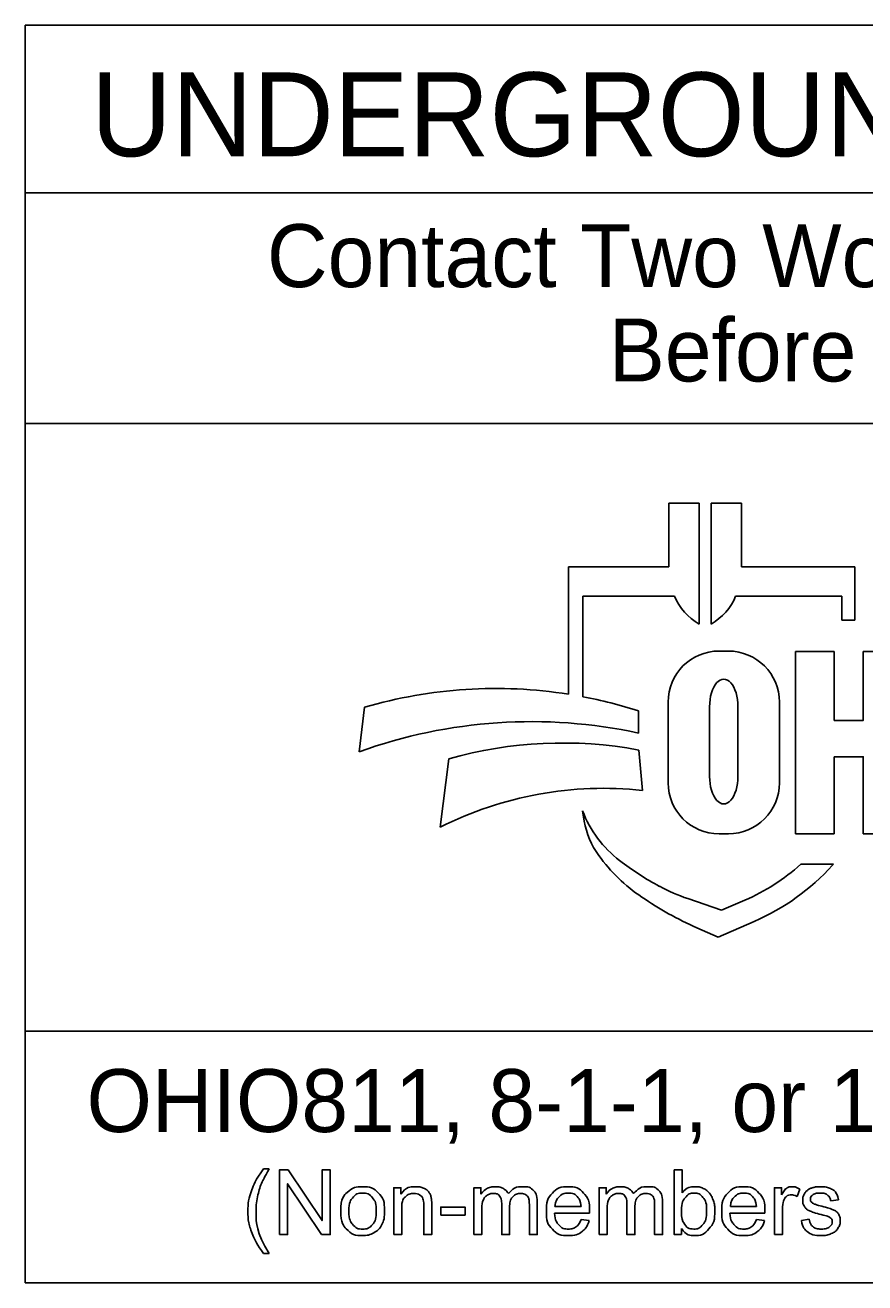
# Model space of a CAD drawing. Extents: x 421.3 to 469.3, y 221.6 to 248.2.
# Drawn here: x 424.333 to 426.536, y 223.579 to 226.879 of the extents above; entities that cross this region are included whole.
import ezdxf

# ---------------------------------------------------------------- set-up
doc = ezdxf.new("R2010")
doc.units = 0
doc.layers.add('SH_Data', color=7, linetype='Continuous')

msp = doc.modelspace()

# ---------------------------------------------------------------- linework, layer by layer
at = {"layer": 'SH_Data'}
for p, q in [((424.3328, 226.8787), (429.5577, 226.8787)), ((424.3328, 223.5787), (424.3328, 226.8787)), ((424.3328, 226.4387), (429.5577, 226.4387)), ((424.3328, 225.8337), (429.5577, 225.8337)), ((426.1017, 225.6241), (426.0216, 225.6241)), ((426.0216, 225.6241), (426.0216, 225.4576)), ((426.1017, 225.3073), (426.1017, 225.6241)), ((426.2129, 225.6241), (426.1328, 225.6241)), ((426.1328, 225.6241), (426.1328, 225.3073)), ((426.2129, 225.4576), (426.2129, 225.6241)), ((426.0216, 225.4576), (425.7587, 225.4576)), ((425.7587, 225.4576), (425.7587, 225.1231)), ((426.5105, 225.4576), (426.2129, 225.4576)), ((426.5105, 225.3174), (426.5105, 225.4576)), ((425.7964, 225.1166), (425.7964, 225.3807)), ((425.7964, 225.3807), (426.0371, 225.3807)), ((426.1973, 225.3807), (426.4758, 225.3807)), ((426.4758, 225.3807), (426.4758, 225.3174)), ((426.4758, 225.3174), (426.5105, 225.3174)), ((426.1784, 225.2364), (426.1537, 225.2364)), ((426.4563, 225.2349), (426.3548, 225.2349)), ((426.3548, 225.2349), (426.3548, 224.7569)), ((426.02, 225.1027), (426.02, 224.8906)), ((426.312, 224.8906), (426.312, 225.1027)), ((425.2236, 225.0889), (425.2096, 224.9722)), ((425.9426, 225.0212), (425.9426, 225.0792)), ((426.1289, 224.9076), (426.1289, 225.0903)), ((426.2033, 225.0903), (426.2033, 224.9076)), ((425.9527, 224.8707), (425.9434, 224.9767)), ((425.4443, 224.9537), (425.4223, 224.7742)), ((426.4563, 224.7569), (426.4563, 224.959)), ((425.7955, 224.8171), (425.8, 224.7903)), ((426.1537, 224.7569), (426.1784, 224.7569)), ((426.3548, 224.7569), (426.4563, 224.7569)), ((426.4539, 224.6769), (426.3681, 224.6769)), ((426.4515, 224.6743), (426.4539, 224.6769)), ((426.1605, 224.5561), (426.0717, 224.5867)), ((426.2218, 224.5827), (426.1605, 224.5561)), ((426.0957, 224.5105), (426.1515, 224.4859)), ((426.1515, 224.4859), (426.246, 224.5269)), ((429.5577, 224.2387), (424.3328, 224.2387)), ((429.5577, 223.5787), (424.3328, 223.5787))]:
    msp.add_line(p, q, dxfattribs=at)
for points in [[(426.4563, 224.959), (426.5324, 224.959), (426.5324, 224.7569), (426.6339, 224.7569), (426.6339, 225.2349), (426.5324, 225.2349), (426.5324, 225.0546), (426.4563, 225.0546), (426.4563, 225.2349)], [(424.9586, 223.8778), (424.9734, 223.8778)], [(425, 223.7055), (425, 223.8749), (425.023, 223.8749), (425.1121, 223.7419), (425.1121, 223.8749), (425.1335, 223.8749), (425.1335, 223.7055), (425.1106, 223.7055), (425.0214, 223.8386), (425.0214, 223.7055), (425, 223.7055)], [(426.0554, 223.7055), (426.0362, 223.7055), (426.0362, 223.8749), (426.057, 223.8749), (426.057, 223.8146)], [(425.3001, 223.7055), (425.3001, 223.8283), (425.3188, 223.8283), (425.3188, 223.8109)], [(425.5104, 223.7055), (425.5104, 223.8283), (425.529, 223.8283), (425.529, 223.811)], [(425.8391, 223.7055), (425.8391, 223.8283), (425.8577, 223.8283), (425.8577, 223.811)], [(426.2992, 223.7055), (426.2992, 223.8283), (426.3179, 223.8283), (426.3179, 223.8097)], [(426.3658, 223.8244), (426.3585, 223.8052)], [(425.3998, 223.781), (425.3998, 223.7055), (425.379, 223.7055), (425.379, 223.7802)], [(425.4234, 223.7564), (425.4234, 223.7773), (425.4874, 223.7773), (425.4874, 223.7564), (425.4234, 223.7564)], [(425.6041, 223.7768), (425.6041, 223.7055), (425.5833, 223.7055), (425.5833, 223.7852)], [(425.6768, 223.7898), (425.6768, 223.7055), (425.656, 223.7055), (425.656, 223.7828)], [(425.7232, 223.7786), (425.7918, 223.7786)], [(425.9329, 223.7768), (425.9329, 223.7055), (425.9121, 223.7055), (425.9121, 223.7852)], [(426.0055, 223.7898), (426.0055, 223.7055), (425.9848, 223.7055), (425.9848, 223.7828)], [(426.1835, 223.7786), (426.252, 223.7786)], [(426.4673, 223.7966), (426.4469, 223.7939)], [(425.3209, 223.7725), (425.3209, 223.7055), (425.3001, 223.7055)], [(425.5312, 223.7692), (425.5312, 223.7055), (425.5104, 223.7055)], [(425.8136, 223.7616), (425.722, 223.7616)], [(425.7915, 223.7452), (425.813, 223.7425)], [(425.8599, 223.7692), (425.8599, 223.7055), (425.8391, 223.7055)], [(426.2739, 223.7616), (426.1823, 223.7616)], [(426.2518, 223.7452), (426.2733, 223.7425)], [(426.32, 223.7698), (426.32, 223.7055), (426.2992, 223.7055)], [(426.3698, 223.7422), (426.3903, 223.7454)], [(426.0554, 223.7209), (426.0554, 223.7055)], [(424.9734, 223.6557), (424.9586, 223.6557)]]:
    msp.add_lwpolyline(points, dxfattribs=at)
for centre, radius, start, end in [((426.1736, 225.4357), 0.1471, 201.9296, 240.7469), ((426.0609, 225.4357), 0.1471, 299.2531, 338.0704), ((426.1537, 225.1027), 0.1337, 90, 180), ((426.1784, 225.1027), 0.1337, 0, 90), ((425.5673, 223.9147), 1.2235, 81.0007, 106.3144), ((425.5673, 223.9147), 1.2235, 72.1402, 79.2074), ((425.6616, 223.7188), 1.3324, 77.8238, 109.8274), ((425.7429, 223.9015), 1.0937, 79.44, 105.8467), ((425.8505, 223.9266), 0.9496, 83.8248, 116.8021), ((426.1537, 224.8906), 0.1337, 180, 270), ((426.1784, 224.8906), 0.1337, 270, 0), ((426.0754, 224.9248), 0.2999, 201.0457, 232.5314), ((426.0111, 224.8263), 0.2141, 189.6817, 216.0884), ((426.2108, 224.9718), 0.4612, 216.0884, 235.7167), ((426.363, 225.3), 0.7728, 232.5314, 241.794), ((426.0075, 225.0764), 0.5381, 293.4582, 312.0712), ((426.0075, 225.0764), 0.599, 293.4582, 317.8286), ((426.2358, 225.0628), 0.5035, 241.794, 250.9821), ((426.4595, 225.3367), 0.9028, 235.7167, 246.2325)]:
    msp.add_arc(centre, radius, start, end, dxfattribs=at)
for centre, start_param, end_param in [((426.1661, 225.0903), 4.712389, 7.853982), ((426.1661, 224.9076), 1.570796, 4.712389)]:
    msp.add_ellipse(centre, major_axis=(0, 0.0723), ratio=0.514403, start_param=start_param, end_param=end_param, dxfattribs=at)
for points in [[(424.9586, 223.6557), (424.9413, 223.6774), (424.9294, 223.7065), (424.9175, 223.7357), (424.9175, 223.7669), (424.9175, 223.7944), (424.9264, 223.8195), (424.9368, 223.8488), (424.9586, 223.8778)], [(424.9734, 223.8778), (424.9595, 223.8537), (424.955, 223.8435), (424.9479, 223.8275), (424.9439, 223.8102), (424.9389, 223.7886), (424.9389, 223.7667), (424.9389, 223.7112), (424.9734, 223.6557)], [(425.1608, 223.7669), (425.1608, 223.801), (425.1797, 223.8174), (425.1955, 223.831), (425.2183, 223.831), (425.2436, 223.831), (425.2596, 223.8145), (425.2757, 223.7979), (425.2757, 223.7687), (425.2757, 223.745), (425.2686, 223.7314), (425.2615, 223.7178), (425.2479, 223.7103), (425.2343, 223.7028), (425.2183, 223.7028), (425.1925, 223.7028), (425.1766, 223.7193), (425.1608, 223.7359), (425.1608, 223.7669)], [(425.1822, 223.7669), (425.1822, 223.7433), (425.1925, 223.7316), (425.2027, 223.7199), (425.2183, 223.7199), (425.2337, 223.7199), (425.244, 223.7317), (425.2542, 223.7435), (425.2542, 223.7676), (425.2542, 223.7904), (425.2439, 223.8021), (425.2336, 223.8139), (425.2183, 223.8139), (425.2027, 223.8139), (425.1925, 223.8022), (425.1822, 223.7905), (425.1822, 223.7669)], [(425.3188, 223.8109), (425.3323, 223.831), (425.3578, 223.831), (425.3689, 223.831), (425.3782, 223.8271), (425.3875, 223.8231), (425.3921, 223.8166), (425.3968, 223.8101), (425.3986, 223.8012), (425.3998, 223.7954), (425.3998, 223.781)], [(425.379, 223.7802), (425.379, 223.7929), (425.3765, 223.7992), (425.3741, 223.8055), (425.3679, 223.8092), (425.3618, 223.813), (425.3534, 223.813), (425.3402, 223.813), (425.3305, 223.8045), (425.3209, 223.7961), (425.3209, 223.7725)], [(425.529, 223.811), (425.5348, 223.82), (425.5444, 223.8255), (425.554, 223.831), (425.5662, 223.831), (425.5798, 223.831), (425.5886, 223.8254), (425.5973, 223.8197), (425.6009, 223.8095), (425.6155, 223.831), (425.6389, 223.831), (425.6571, 223.831), (425.667, 223.8209), (425.6768, 223.8108), (425.6768, 223.7898)], [(425.5833, 223.7852), (425.5833, 223.7991), (425.5782, 223.806), (425.5732, 223.813), (425.5616, 223.813), (425.5528, 223.813), (425.5453, 223.8083), (425.5379, 223.8037), (425.5345, 223.7948), (425.5312, 223.7859), (425.5312, 223.7692)], [(425.656, 223.7828), (425.656, 223.7953), (425.654, 223.8008), (425.652, 223.8063), (425.6467, 223.8096), (425.6413, 223.813), (425.6342, 223.813), (425.6212, 223.813), (425.6127, 223.8044), (425.6041, 223.7958), (425.6041, 223.7768)], [(425.813, 223.7425), (425.8079, 223.7236), (425.7942, 223.7132), (425.7804, 223.7028), (425.7591, 223.7028), (425.7321, 223.7028), (425.7164, 223.7194), (425.7006, 223.736), (425.7006, 223.7659), (425.7006, 223.7969), (425.7165, 223.8139), (425.7325, 223.831), (425.7579, 223.831), (425.7825, 223.831), (425.7981, 223.8143), (425.8137, 223.7975), (425.8137, 223.7671), (425.8137, 223.7653), (425.8136, 223.7616)], [(425.7918, 223.7786), (425.7904, 223.7942), (425.7839, 223.8019), (425.7739, 223.814), (425.7581, 223.814), (425.7438, 223.814), (425.734, 223.8044), (425.7242, 223.7947), (425.7232, 223.7786)], [(425.8577, 223.811), (425.8635, 223.82), (425.8731, 223.8255), (425.8827, 223.831), (425.8949, 223.831), (425.9086, 223.831), (425.9173, 223.8254), (425.926, 223.8197), (425.9296, 223.8095), (425.9442, 223.831), (425.9676, 223.831), (425.9859, 223.831), (425.9957, 223.8209), (426.0055, 223.8108), (426.0055, 223.7898)], [(425.9121, 223.7852), (425.9121, 223.7991), (425.907, 223.806), (425.9019, 223.813), (425.8903, 223.813), (425.8815, 223.813), (425.8741, 223.8083), (425.8666, 223.8037), (425.8633, 223.7948), (425.8599, 223.7859), (425.8599, 223.7692)], [(425.9848, 223.7828), (425.9848, 223.7953), (425.9827, 223.8008), (425.9807, 223.8063), (425.9754, 223.8096), (425.9701, 223.813), (425.9629, 223.813), (425.95, 223.813), (425.9414, 223.8044), (425.9329, 223.7958), (425.9329, 223.7768)], [(426.0551, 223.7679), (426.0551, 223.7458), (426.0611, 223.7359), (426.071, 223.7199), (426.0877, 223.7199), (426.1013, 223.7199), (426.1112, 223.7317), (426.1211, 223.7436), (426.1211, 223.7671), (426.1211, 223.7911), (426.1116, 223.8026), (426.1021, 223.814), (426.0886, 223.814), (426.075, 223.814), (426.0651, 223.8021), (426.0551, 223.7903), (426.0551, 223.7679)], [(426.057, 223.8146), (426.0701, 223.831), (426.0906, 223.831), (426.1019, 223.831), (426.112, 223.8265), (426.1221, 223.8219), (426.1286, 223.8137), (426.1352, 223.8054), (426.1389, 223.7937), (426.1426, 223.7821), (426.1426, 223.7688), (426.1426, 223.7373), (426.127, 223.72), (426.1114, 223.7028), (426.0895, 223.7028), (426.0678, 223.7028), (426.0554, 223.7209)], [(426.2733, 223.7425), (426.2682, 223.7236), (426.2545, 223.7132), (426.2407, 223.7028), (426.2194, 223.7028), (426.1924, 223.7028), (426.1767, 223.7194), (426.1609, 223.736), (426.1609, 223.7659), (426.1609, 223.7969), (426.1768, 223.8139), (426.1928, 223.831), (426.2182, 223.831), (426.2428, 223.831), (426.2584, 223.8143), (426.274, 223.7975), (426.274, 223.7671), (426.274, 223.7653), (426.2739, 223.7616)], [(426.252, 223.7786), (426.2507, 223.7942), (426.2442, 223.8019), (426.2342, 223.814), (426.2184, 223.814), (426.2041, 223.814), (426.1943, 223.8044), (426.1845, 223.7947), (426.1835, 223.7786)], [(426.3179, 223.8097), (426.3251, 223.8227), (426.3311, 223.8269), (426.3372, 223.831), (426.3444, 223.831), (426.355, 223.831), (426.3658, 223.8244)], [(426.3585, 223.8052), (426.3509, 223.8096), (426.3433, 223.8096), (426.3365, 223.8096), (426.3311, 223.8055), (426.3257, 223.8014), (426.3234, 223.7941), (426.32, 223.783), (426.32, 223.7698)], [(426.4469, 223.7939), (426.4455, 223.8033), (426.4388, 223.8087), (426.4322, 223.814), (426.42, 223.814), (426.4057, 223.814), (426.3996, 223.8093), (426.3934, 223.8045), (426.3934, 223.7981), (426.3934, 223.7941), (426.396, 223.7908), (426.3985, 223.7875), (426.404, 223.7853), (426.4071, 223.7841), (426.4224, 223.78), (426.4445, 223.7741), (426.4532, 223.7703), (426.462, 223.7666), (426.4669, 223.7594), (426.4719, 223.7523), (426.4719, 223.7416), (426.4719, 223.7312), (426.4659, 223.7221), (426.4598, 223.7129), (426.4483, 223.7079), (426.4368, 223.7028), (426.4224, 223.7028), (426.3984, 223.7028), (426.3858, 223.7128), (426.3733, 223.7227), (426.3698, 223.7422)], [(426.3903, 223.7454), (426.3921, 223.7331), (426.4, 223.7265), (426.408, 223.7199), (426.4222, 223.7199), (426.4366, 223.7199), (426.4435, 223.7257), (426.4505, 223.7316), (426.4505, 223.7394), (426.4505, 223.7465), (426.4444, 223.7505), (426.4401, 223.7533), (426.423, 223.7576), (426.4001, 223.7634), (426.3913, 223.7676), (426.3824, 223.7718), (426.3779, 223.7793), (426.3733, 223.7867), (426.3733, 223.7957), (426.3733, 223.8039), (426.3771, 223.8109), (426.3808, 223.8179), (426.3873, 223.8225), (426.3922, 223.8261), (426.4006, 223.8286), (426.4089, 223.831), (426.4186, 223.831), (426.433, 223.831), (426.444, 223.8269), (426.4549, 223.8227), (426.4601, 223.8156), (426.4653, 223.8085), (426.4673, 223.7966)], [(425.722, 223.7616), (425.7232, 223.7414), (425.7335, 223.7306), (425.7438, 223.7199), (425.7591, 223.7199), (425.7706, 223.7199), (425.7787, 223.7259), (425.7868, 223.7319), (425.7915, 223.7452)], [(426.1823, 223.7616), (426.1835, 223.7414), (426.1938, 223.7306), (426.2041, 223.7199), (426.2194, 223.7199), (426.2309, 223.7199), (426.239, 223.7259), (426.2471, 223.7319), (426.2518, 223.7452)]]:
    msp.add_open_spline(points, degree=3, dxfattribs=at)

# ---------------------------------------------------------------- texts
for s, height, p in [('UNDERGROUND UTILITIES', 0.22, (424.5053, 226.5347)), ('Contact Two Working Days', 0.165, (424.9672, 226.1913)), ('Before You Dig', 0.165, (425.8643, 225.9438)), ('OHIO811, 8-1-1, or 1-800-362-2764', 0.165, (424.4938, 223.9744))]:
    msp.add_text(s, height=height, dxfattribs=at).set_placement(p)

doc.saveas('drawing.dxf')
